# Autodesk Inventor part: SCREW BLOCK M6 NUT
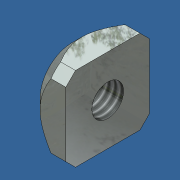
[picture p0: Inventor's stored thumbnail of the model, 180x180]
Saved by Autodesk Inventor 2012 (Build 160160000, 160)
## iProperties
Created: 2015-03
Part Number: SCREW BLOCK M6 NUT
Material: Steel
Document SubType Name: Modeling
Designer: Admin
Density: 7.85 g/cm^3
Mass: 5.41294 g
Surface Area: 5.67779 cm^2
Volume: 0.689546 cm^3
Author: Admin
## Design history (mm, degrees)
feature "Base1"
sketch "Sketch1"
  geometry: C1 r 2.952 at (-6.5, 4.998) reference; C2 r 0.735 at (-6.5, 4.998); 1 further point
  constraints: 1 centre point, 1 coincident
extrude "Extrusion1" join sketch "Sketch1" stored distance "d0" = 10; taper "d1" = 0 deg
sketch "Sketch2"
  geometry: C1 r 0.735 at (-6.5, 4.998) reference; 2 further points
  constraints: 1 coincident
hole "Hole1" sketch "Sketch2" at (-6.5, 4.998) diameter "d2" = 4.917; stored, may be unused: countersink angle "d6" = 90 deg, drill point angle "d8" = 118 deg; dims "d3" = 6, "d4" = 4, "d5" = 2, "d7" = 8
body "Solid1"
